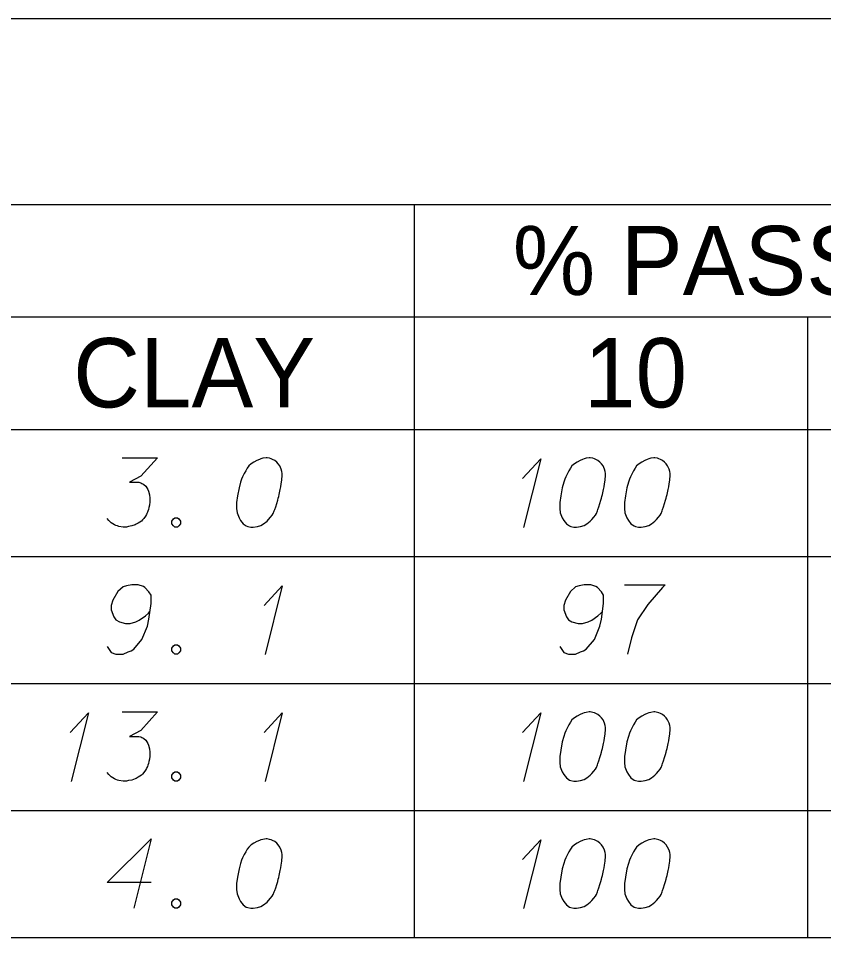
# Model space of a CAD drawing. Extents: x 2074207 to 2076812, y 516372 to 523312.
# Drawn here: x 2076622.7 to 2076678.5, y 516677.4 to 516741.1 of the extents above; entities that cross this region are included whole.
import ezdxf

# ---------------------------------------------------------------- set-up
doc = ezdxf.new("R2010")
doc.units = 0
for name, color, linetype in [('Prop DirtTable_ Soil Test Results - Outline (Major)', 7, 'Continuous'), ('Prop DirtTable_ Soil Test Results - Outline (Minor)', 7, 'Continuous'), ('Prop DirtTable_ Soil Test Results - Tx (Header - Small)', 7, 'Continuous'), ('Prop DirtTable_ Soil Test Results - Tx (Sample Data)', 7, 'Continuous')]:
    doc.layers.add(name, color=color, linetype=linetype)

msp = doc.modelspace()

# ---------------------------------------------------------------- linework, layer by layer
at = {"layer": 'Prop DirtTable_ Soil Test Results - Outline (Major)'}
for p, q in [((2076260.609, 516741.103), (2076811.903, 516741.103)), ((2076260.609, 516712.618), (2076811.903, 516712.618)), ((2076260.609, 516712.618), (2076811.903, 516712.618)), ((2076260.609, 516677.418), (2076811.903, 516677.418))]:
    msp.add_line(p, q, dxfattribs=at)
at = {"layer": 'Prop DirtTable_ Soil Test Results - Outline (Minor)'}
for p, q in [((2076260.609, 516728.218), (2076811.903, 516728.218)), ((2076650.154, 516728.218), (2076650.154, 516703.818)), ((2076526.074, 516720.418), (2076731.93, 516720.418)), ((2076677.413, 516720.418), (2076677.413, 516703.818)), ((2076260.609, 516703.818), (2076811.903, 516703.818)), ((2076260.609, 516703.818), (2076811.903, 516703.818)), ((2076650.154, 516703.818), (2076650.154, 516695.018)), ((2076677.413, 516703.818), (2076677.413, 516695.018)), ((2076260.609, 516695.018), (2076811.903, 516695.018)), ((2076260.609, 516695.018), (2076811.903, 516695.018)), ((2076650.154, 516695.018), (2076650.154, 516686.218)), ((2076677.413, 516695.018), (2076677.413, 516686.218)), ((2076260.609, 516686.218), (2076811.903, 516686.218)), ((2076260.609, 516686.218), (2076811.903, 516686.218)), ((2076650.154, 516686.218), (2076650.154, 516677.418)), ((2076677.413, 516686.218), (2076677.413, 516677.418)), ((2076260.609, 516677.418), (2076811.903, 516677.418))]:
    msp.add_line(p, q, dxfattribs=at)
at = {"layer": 'Prop DirtTable_ Soil Test Results - Tx (Sample Data)'}
for points in [[(2076629.899, 516710.662), (2076632.368, 516710.662), (2076631.204, 516709.377), (2076630.428, 516708.961), (2076631.063, 516708.961), (2076631.204, 516708.923), (2076631.274, 516708.885), (2076631.345, 516708.848), (2076631.415, 516708.81), (2076631.557, 516708.696), (2076631.627, 516708.583), (2076631.698, 516708.47), (2076631.733, 516708.356), (2076631.803, 516708.092), (2076631.839, 516707.865), (2076631.839, 516707.751), (2076631.839, 516707.6), (2076631.803, 516707.373), (2076631.768, 516707.222), (2076631.733, 516707.071), (2076631.698, 516706.958), (2076631.662, 516706.882), (2076631.627, 516706.807), (2076631.592, 516706.731), (2076631.521, 516706.618), (2076631.415, 516706.466), (2076631.31, 516706.353), (2076631.239, 516706.277), (2076631.133, 516706.202), (2076631.027, 516706.126), (2076630.886, 516706.051), (2076630.816, 516706.013), (2076630.569, 516705.937), (2076630.357, 516705.899), (2076630.216, 516705.862), (2076629.969, 516705.862), (2076629.687, 516705.899), (2076629.581, 516705.937), (2076629.475, 516705.975), (2076629.369, 516706.013), (2076629.264, 516706.088), (2076629.158, 516706.164), (2076628.981, 516706.315), (2076628.876, 516706.466)], [(2076639.952, 516710.662), (2076639.882, 516710.662), (2076639.67, 516710.624), (2076639.529, 516710.586), (2076639.423, 516710.548), (2076639.247, 516710.473), (2076639.035, 516710.359), (2076638.859, 516710.246), (2076638.682, 516710.095), (2076638.576, 516709.944), (2076638.471, 516709.755), (2076638.365, 516709.566), (2076638.259, 516709.339), (2076638.188, 516709.188), (2076638.118, 516708.961), (2076638.012, 516708.583), (2076637.906, 516708.016), (2076637.836, 516707.562), (2076637.836, 516707.147), (2076637.871, 516706.844), (2076638.012, 516706.504), (2076638.118, 516706.315), (2076638.294, 516706.088), (2076638.506, 516705.937), (2076638.612, 516705.899), (2076638.823, 516705.862), (2076639, 516705.862), (2076639.282, 516705.899), (2076639.529, 516705.975), (2076639.705, 516706.088), (2076639.952, 516706.277), (2076640.058, 516706.391), (2076640.199, 516706.542), (2076640.305, 516706.693), (2076640.375, 516706.807), (2076640.446, 516706.996), (2076640.481, 516707.071), (2076640.552, 516707.26), (2076640.622, 516707.487), (2076640.693, 516707.714), (2076640.728, 516707.865), (2076640.763, 516707.978), (2076640.799, 516708.129), (2076640.869, 516708.47), (2076640.905, 516708.659), (2076640.94, 516708.848), (2076640.975, 516709.112), (2076641.01, 516709.452), (2076641.01, 516709.566), (2076640.975, 516709.717), (2076640.94, 516709.868), (2076640.834, 516710.095), (2076640.728, 516710.246), (2076640.622, 516710.359), (2076640.481, 516710.473), (2076640.34, 516710.548), (2076640.234, 516710.586), (2076640.129, 516710.624), (2076639.952, 516710.662)], [(2076657.66, 516709.225), (2076658.93, 516710.586), (2076657.731, 516705.824)], [(2076662.352, 516710.662), (2076662.282, 516710.662), (2076662.07, 516710.624), (2076661.929, 516710.586), (2076661.823, 516710.548), (2076661.647, 516710.473), (2076661.435, 516710.359), (2076661.259, 516710.246), (2076661.082, 516710.095), (2076660.976, 516709.944), (2076660.871, 516709.755), (2076660.765, 516709.566), (2076660.659, 516709.339), (2076660.588, 516709.188), (2076660.518, 516708.961), (2076660.412, 516708.583), (2076660.306, 516708.016), (2076660.236, 516707.562), (2076660.236, 516707.147), (2076660.271, 516706.844), (2076660.412, 516706.504), (2076660.518, 516706.315), (2076660.694, 516706.088), (2076660.906, 516705.937), (2076661.012, 516705.899), (2076661.223, 516705.862), (2076661.4, 516705.862), (2076661.682, 516705.899), (2076661.929, 516705.975), (2076662.105, 516706.088), (2076662.352, 516706.277), (2076662.458, 516706.391), (2076662.599, 516706.542), (2076662.705, 516706.693), (2076662.775, 516706.807), (2076662.846, 516706.996), (2076662.881, 516707.071), (2076662.952, 516707.26), (2076663.022, 516707.487), (2076663.093, 516707.714), (2076663.128, 516707.865), (2076663.163, 516707.978), (2076663.199, 516708.129), (2076663.269, 516708.47), (2076663.305, 516708.659), (2076663.34, 516708.848), (2076663.375, 516709.112), (2076663.41, 516709.452), (2076663.41, 516709.566), (2076663.375, 516709.717), (2076663.34, 516709.868), (2076663.234, 516710.095), (2076663.128, 516710.246), (2076663.022, 516710.359), (2076662.881, 516710.473), (2076662.74, 516710.548), (2076662.634, 516710.586), (2076662.529, 516710.624), (2076662.352, 516710.662)], [(2076666.832, 516710.662), (2076666.762, 516710.662), (2076666.55, 516710.624), (2076666.409, 516710.586), (2076666.303, 516710.548), (2076666.127, 516710.473), (2076665.915, 516710.359), (2076665.739, 516710.246), (2076665.562, 516710.095), (2076665.456, 516709.944), (2076665.351, 516709.755), (2076665.245, 516709.566), (2076665.139, 516709.339), (2076665.068, 516709.188), (2076664.998, 516708.961), (2076664.892, 516708.583), (2076664.786, 516708.016), (2076664.716, 516707.562), (2076664.716, 516707.147), (2076664.751, 516706.844), (2076664.892, 516706.504), (2076664.998, 516706.315), (2076665.174, 516706.088), (2076665.386, 516705.937), (2076665.492, 516705.899), (2076665.703, 516705.862), (2076665.88, 516705.862), (2076666.162, 516705.899), (2076666.409, 516705.975), (2076666.585, 516706.088), (2076666.832, 516706.277), (2076666.938, 516706.391), (2076667.079, 516706.542), (2076667.185, 516706.693), (2076667.255, 516706.807), (2076667.326, 516706.996), (2076667.361, 516707.071), (2076667.432, 516707.26), (2076667.502, 516707.487), (2076667.573, 516707.714), (2076667.608, 516707.865), (2076667.643, 516707.978), (2076667.679, 516708.129), (2076667.749, 516708.47), (2076667.785, 516708.659), (2076667.82, 516708.848), (2076667.855, 516709.112), (2076667.89, 516709.452), (2076667.89, 516709.566), (2076667.855, 516709.717), (2076667.82, 516709.868), (2076667.714, 516710.095), (2076667.608, 516710.246), (2076667.502, 516710.359), (2076667.361, 516710.473), (2076667.22, 516710.548), (2076667.114, 516710.586), (2076667.009, 516710.624), (2076666.832, 516710.662)], [(2076633.567, 516706.504), (2076633.744, 516706.504), (2076633.849, 516706.429), (2076633.955, 516706.277), (2076633.955, 516706.088), (2076633.849, 516705.937), (2076633.744, 516705.862), (2076633.567, 516705.862), (2076633.461, 516705.937), (2076633.356, 516706.088), (2076633.356, 516706.277), (2076633.461, 516706.429), (2076633.567, 516706.504)], [(2076628.876, 516697.591), (2076629.158, 516697.175), (2076629.475, 516697.062), (2076629.969, 516697.062), (2076630.322, 516697.213), (2076630.534, 516697.288), (2076630.71, 516697.402), (2076631.274, 516698.082), (2076631.662, 516698.989), (2076631.768, 516699.481), (2076631.909, 516700.577), (2076631.909, 516701.144), (2076631.768, 516701.37), (2076631.486, 516701.673), (2076631.38, 516701.748), (2076631.027, 516701.862), (2076630.569, 516701.862), (2076630.216, 516701.786), (2076629.969, 516701.711), (2076629.616, 516701.408), (2076629.264, 516700.803), (2076629.158, 516700.425), (2076629.158, 516700.123), (2076629.334, 516699.632), (2076629.475, 516699.443), (2076629.722, 516699.292), (2076630.146, 516699.178), (2076630.463, 516699.178), (2076630.851, 516699.292), (2076631.098, 516699.405), (2076631.521, 516699.707), (2076631.733, 516699.896), (2076631.839, 516700.01)], [(2076639.74, 516700.425), (2076641.01, 516701.786), (2076639.811, 516697.024)], [(2076660.236, 516697.591), (2076660.518, 516697.175), (2076660.835, 516697.062), (2076661.329, 516697.062), (2076661.682, 516697.213), (2076661.894, 516697.288), (2076662.07, 516697.402), (2076662.634, 516698.082), (2076663.022, 516698.989), (2076663.128, 516699.481), (2076663.269, 516700.577), (2076663.269, 516701.144), (2076663.128, 516701.37), (2076662.846, 516701.673), (2076662.74, 516701.748), (2076662.387, 516701.862), (2076661.929, 516701.862), (2076661.576, 516701.786), (2076661.329, 516701.711), (2076660.976, 516701.408), (2076660.624, 516700.803), (2076660.518, 516700.425), (2076660.518, 516700.123), (2076660.694, 516699.632), (2076660.835, 516699.443), (2076661.082, 516699.292), (2076661.506, 516699.178), (2076661.823, 516699.178), (2076662.211, 516699.292), (2076662.458, 516699.405), (2076662.881, 516699.707), (2076663.093, 516699.896), (2076663.199, 516700.01)], [(2076664.716, 516701.862), (2076667.538, 516701.862), (2076667.361, 516701.673), (2076666.338, 516700.501), (2076665.633, 516699.443), (2076665.209, 516698.196), (2076664.927, 516697.062)], [(2076633.567, 516697.704), (2076633.744, 516697.704), (2076633.849, 516697.629), (2076633.955, 516697.477), (2076633.955, 516697.288), (2076633.849, 516697.137), (2076633.744, 516697.062), (2076633.567, 516697.062), (2076633.461, 516697.137), (2076633.356, 516697.288), (2076633.356, 516697.477), (2076633.461, 516697.629), (2076633.567, 516697.704)], [(2076629.899, 516693.062), (2076632.368, 516693.062), (2076631.204, 516691.777), (2076630.428, 516691.361), (2076631.063, 516691.361), (2076631.204, 516691.323), (2076631.274, 516691.285), (2076631.345, 516691.248), (2076631.415, 516691.21), (2076631.557, 516691.096), (2076631.627, 516690.983), (2076631.698, 516690.87), (2076631.733, 516690.756), (2076631.803, 516690.492), (2076631.839, 516690.265), (2076631.839, 516690.151), (2076631.839, 516690), (2076631.803, 516689.773), (2076631.768, 516689.622), (2076631.733, 516689.471), (2076631.698, 516689.358), (2076631.662, 516689.282), (2076631.627, 516689.207), (2076631.592, 516689.131), (2076631.521, 516689.018), (2076631.415, 516688.866), (2076631.31, 516688.753), (2076631.239, 516688.677), (2076631.133, 516688.602), (2076631.027, 516688.526), (2076630.886, 516688.451), (2076630.816, 516688.413), (2076630.569, 516688.337), (2076630.357, 516688.299), (2076630.216, 516688.262), (2076629.969, 516688.262), (2076629.687, 516688.299), (2076629.581, 516688.337), (2076629.475, 516688.375), (2076629.369, 516688.413), (2076629.264, 516688.488), (2076629.158, 516688.564), (2076628.981, 516688.715), (2076628.876, 516688.866)], [(2076662.352, 516693.062), (2076662.282, 516693.062), (2076662.07, 516693.024), (2076661.929, 516692.986), (2076661.823, 516692.948), (2076661.647, 516692.873), (2076661.435, 516692.759), (2076661.259, 516692.646), (2076661.082, 516692.495), (2076660.976, 516692.344), (2076660.871, 516692.155), (2076660.765, 516691.966), (2076660.659, 516691.739), (2076660.588, 516691.588), (2076660.518, 516691.361), (2076660.412, 516690.983), (2076660.306, 516690.416), (2076660.236, 516689.962), (2076660.236, 516689.547), (2076660.271, 516689.244), (2076660.412, 516688.904), (2076660.518, 516688.715), (2076660.694, 516688.488), (2076660.906, 516688.337), (2076661.012, 516688.299), (2076661.223, 516688.262), (2076661.4, 516688.262), (2076661.682, 516688.299), (2076661.929, 516688.375), (2076662.105, 516688.488), (2076662.352, 516688.677), (2076662.458, 516688.791), (2076662.599, 516688.942), (2076662.705, 516689.093), (2076662.775, 516689.207), (2076662.846, 516689.396), (2076662.881, 516689.471), (2076662.952, 516689.66), (2076663.022, 516689.887), (2076663.093, 516690.114), (2076663.128, 516690.265), (2076663.163, 516690.378), (2076663.199, 516690.529), (2076663.269, 516690.87), (2076663.305, 516691.059), (2076663.34, 516691.248), (2076663.375, 516691.512), (2076663.41, 516691.852), (2076663.41, 516691.966), (2076663.375, 516692.117), (2076663.34, 516692.268), (2076663.234, 516692.495), (2076663.128, 516692.646), (2076663.022, 516692.759), (2076662.881, 516692.873), (2076662.74, 516692.948), (2076662.634, 516692.986), (2076662.529, 516693.024), (2076662.352, 516693.062)], [(2076666.832, 516693.062), (2076666.762, 516693.062), (2076666.55, 516693.024), (2076666.409, 516692.986), (2076666.303, 516692.948), (2076666.127, 516692.873), (2076665.915, 516692.759), (2076665.739, 516692.646), (2076665.562, 516692.495), (2076665.456, 516692.344), (2076665.351, 516692.155), (2076665.245, 516691.966), (2076665.139, 516691.739), (2076665.068, 516691.588), (2076664.998, 516691.361), (2076664.892, 516690.983), (2076664.786, 516690.416), (2076664.716, 516689.962), (2076664.716, 516689.547), (2076664.751, 516689.244), (2076664.892, 516688.904), (2076664.998, 516688.715), (2076665.174, 516688.488), (2076665.386, 516688.337), (2076665.492, 516688.299), (2076665.703, 516688.262), (2076665.88, 516688.262), (2076666.162, 516688.299), (2076666.409, 516688.375), (2076666.585, 516688.488), (2076666.832, 516688.677), (2076666.938, 516688.791), (2076667.079, 516688.942), (2076667.185, 516689.093), (2076667.255, 516689.207), (2076667.326, 516689.396), (2076667.361, 516689.471), (2076667.432, 516689.66), (2076667.502, 516689.887), (2076667.573, 516690.114), (2076667.608, 516690.265), (2076667.643, 516690.378), (2076667.679, 516690.529), (2076667.749, 516690.87), (2076667.785, 516691.059), (2076667.82, 516691.248), (2076667.855, 516691.512), (2076667.89, 516691.852), (2076667.89, 516691.966), (2076667.855, 516692.117), (2076667.82, 516692.268), (2076667.714, 516692.495), (2076667.608, 516692.646), (2076667.502, 516692.759), (2076667.361, 516692.873), (2076667.22, 516692.948), (2076667.114, 516692.986), (2076667.009, 516693.024), (2076666.832, 516693.062)], [(2076626.3, 516691.625), (2076627.57, 516692.986), (2076626.371, 516688.224)], [(2076639.74, 516691.625), (2076641.01, 516692.986), (2076639.811, 516688.224)], [(2076657.66, 516691.625), (2076658.93, 516692.986), (2076657.731, 516688.224)], [(2076633.567, 516688.904), (2076633.744, 516688.904), (2076633.849, 516688.829), (2076633.955, 516688.677), (2076633.955, 516688.488), (2076633.849, 516688.337), (2076633.744, 516688.262), (2076633.567, 516688.262), (2076633.461, 516688.337), (2076633.356, 516688.488), (2076633.356, 516688.677), (2076633.461, 516688.829), (2076633.567, 516688.904)], [(2076631.909, 516681.238), (2076628.876, 516681.238), (2076631.909, 516684.262), (2076630.71, 516679.462)], [(2076639.952, 516684.262), (2076639.882, 516684.262), (2076639.67, 516684.224), (2076639.529, 516684.186), (2076639.423, 516684.148), (2076639.247, 516684.073), (2076639.035, 516683.959), (2076638.859, 516683.846), (2076638.682, 516683.695), (2076638.576, 516683.544), (2076638.471, 516683.355), (2076638.365, 516683.166), (2076638.259, 516682.939), (2076638.188, 516682.788), (2076638.118, 516682.561), (2076638.012, 516682.183), (2076637.906, 516681.616), (2076637.836, 516681.162), (2076637.836, 516680.747), (2076637.871, 516680.444), (2076638.012, 516680.104), (2076638.118, 516679.915), (2076638.294, 516679.688), (2076638.506, 516679.537), (2076638.612, 516679.499), (2076638.823, 516679.462), (2076639, 516679.462), (2076639.282, 516679.499), (2076639.529, 516679.575), (2076639.705, 516679.688), (2076639.952, 516679.877), (2076640.058, 516679.991), (2076640.199, 516680.142), (2076640.305, 516680.293), (2076640.375, 516680.407), (2076640.446, 516680.596), (2076640.481, 516680.671), (2076640.552, 516680.86), (2076640.622, 516681.087), (2076640.693, 516681.314), (2076640.728, 516681.465), (2076640.763, 516681.578), (2076640.799, 516681.729), (2076640.869, 516682.07), (2076640.905, 516682.259), (2076640.94, 516682.448), (2076640.975, 516682.712), (2076641.01, 516683.052), (2076641.01, 516683.166), (2076640.975, 516683.317), (2076640.94, 516683.468), (2076640.834, 516683.695), (2076640.728, 516683.846), (2076640.622, 516683.959), (2076640.481, 516684.073), (2076640.34, 516684.148), (2076640.234, 516684.186), (2076640.129, 516684.224), (2076639.952, 516684.262)], [(2076657.66, 516682.825), (2076658.93, 516684.186), (2076657.731, 516679.424)], [(2076662.352, 516684.262), (2076662.282, 516684.262), (2076662.07, 516684.224), (2076661.929, 516684.186), (2076661.823, 516684.148), (2076661.647, 516684.073), (2076661.435, 516683.959), (2076661.259, 516683.846), (2076661.082, 516683.695), (2076660.976, 516683.544), (2076660.871, 516683.355), (2076660.765, 516683.166), (2076660.659, 516682.939), (2076660.588, 516682.788), (2076660.518, 516682.561), (2076660.412, 516682.183), (2076660.306, 516681.616), (2076660.236, 516681.162), (2076660.236, 516680.747), (2076660.271, 516680.444), (2076660.412, 516680.104), (2076660.518, 516679.915), (2076660.694, 516679.688), (2076660.906, 516679.537), (2076661.012, 516679.499), (2076661.223, 516679.462), (2076661.4, 516679.462), (2076661.682, 516679.499), (2076661.929, 516679.575), (2076662.105, 516679.688), (2076662.352, 516679.877), (2076662.458, 516679.991), (2076662.599, 516680.142), (2076662.705, 516680.293), (2076662.775, 516680.407), (2076662.846, 516680.596), (2076662.881, 516680.671), (2076662.952, 516680.86), (2076663.022, 516681.087), (2076663.093, 516681.314), (2076663.128, 516681.465), (2076663.163, 516681.578), (2076663.199, 516681.729), (2076663.269, 516682.07), (2076663.305, 516682.259), (2076663.34, 516682.448), (2076663.375, 516682.712), (2076663.41, 516683.052), (2076663.41, 516683.166), (2076663.375, 516683.317), (2076663.34, 516683.468), (2076663.234, 516683.695), (2076663.128, 516683.846), (2076663.022, 516683.959), (2076662.881, 516684.073), (2076662.74, 516684.148), (2076662.634, 516684.186), (2076662.529, 516684.224), (2076662.352, 516684.262)], [(2076666.832, 516684.262), (2076666.762, 516684.262), (2076666.55, 516684.224), (2076666.409, 516684.186), (2076666.303, 516684.148), (2076666.127, 516684.073), (2076665.915, 516683.959), (2076665.739, 516683.846), (2076665.562, 516683.695), (2076665.456, 516683.544), (2076665.351, 516683.355), (2076665.245, 516683.166), (2076665.139, 516682.939), (2076665.068, 516682.788), (2076664.998, 516682.561), (2076664.892, 516682.183), (2076664.786, 516681.616), (2076664.716, 516681.162), (2076664.716, 516680.747), (2076664.751, 516680.444), (2076664.892, 516680.104), (2076664.998, 516679.915), (2076665.174, 516679.688), (2076665.386, 516679.537), (2076665.492, 516679.499), (2076665.703, 516679.462), (2076665.88, 516679.462), (2076666.162, 516679.499), (2076666.409, 516679.575), (2076666.585, 516679.688), (2076666.832, 516679.877), (2076666.938, 516679.991), (2076667.079, 516680.142), (2076667.185, 516680.293), (2076667.255, 516680.407), (2076667.326, 516680.596), (2076667.361, 516680.671), (2076667.432, 516680.86), (2076667.502, 516681.087), (2076667.573, 516681.314), (2076667.608, 516681.465), (2076667.643, 516681.578), (2076667.679, 516681.729), (2076667.749, 516682.07), (2076667.785, 516682.259), (2076667.82, 516682.448), (2076667.855, 516682.712), (2076667.89, 516683.052), (2076667.89, 516683.166), (2076667.855, 516683.317), (2076667.82, 516683.468), (2076667.714, 516683.695), (2076667.608, 516683.846), (2076667.502, 516683.959), (2076667.361, 516684.073), (2076667.22, 516684.148), (2076667.114, 516684.186), (2076667.009, 516684.224), (2076666.832, 516684.262)], [(2076633.567, 516680.104), (2076633.744, 516680.104), (2076633.849, 516680.029), (2076633.955, 516679.877), (2076633.955, 516679.688), (2076633.849, 516679.537), (2076633.744, 516679.462), (2076633.567, 516679.462), (2076633.461, 516679.537), (2076633.356, 516679.688), (2076633.356, 516679.877), (2076633.461, 516680.029), (2076633.567, 516680.104)]]:
    msp.add_lwpolyline(points, dxfattribs=at)

# ---------------------------------------------------------------- texts
at = {"layer": 'Prop DirtTable_ Soil Test Results - Tx (Header - Small)'}
for s, height, p in [('% PASSING (SIEVES)', 4.79998, (2076656.984, 516721.928)), ('CLAY', 4.8, (2076626.513, 516714.153)), ('10', 4.8, (2076661.92, 516714.153))]:
    msp.add_text(s, height=height, dxfattribs=at).set_placement(p)

doc.saveas('drawing.dxf')
